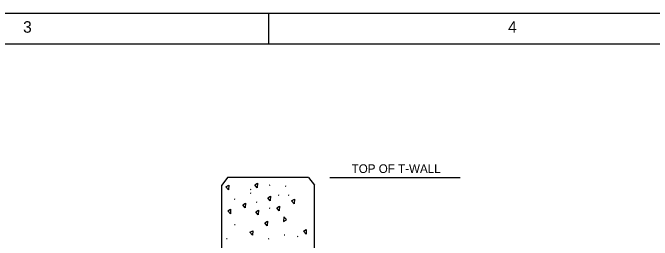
# Model space of a CAD drawing. Extents: x 22369.6 to 22389.4, y 22369.6 to 22386.
# Drawn here: x 22376.584 to 22380.038, y 22379.725 to 22380.956 of the extents above; entities that cross this region are included whole.
import ezdxf

# ---------------------------------------------------------------- set-up
doc = ezdxf.new("R2010")
doc.units = 0
for name, color, linetype in [('Level 1', 7, 'Continuous'), ('Level 10', 7, 'Continuous'), ('Level 4', 7, 'Continuous'), ('Level 44', 7, 'Continuous'), ('Level 7', 7, 'Continuous'), ('Level 9', 7, 'Continuous')]:
    doc.layers.add(name, color=color, linetype=linetype)

msp = doc.modelspace()

# ---------------------------------------------------------------- linework, layer by layer
at = {"layer": 'Level 1'}
msp.add_line((22378.2968, 22380.0639), (22379.0009, 22380.0639), dxfattribs=at)
msp.add_lwpolyline([(22369.6213, 22380.9546), (22384.2881, 22380.9546), (22384.2881, 22369.6213), (22369.6213, 22369.6213)], close=True, dxfattribs=at)
at = {"layer": 'Level 10'}
msp.add_line((22377.9681, 22380.788), (22377.9681, 22380.956), dxfattribs=at)
at = {"layer": 'Level 44'}
for p, q in [((22377.9705, 22380.0221), (22377.9743, 22380.0244)), ((22378.055, 22380.0189), (22378.059, 22380.0169)), ((22377.866, 22379.9811), (22377.87, 22379.9791)), ((22377.8687, 22379.9991), (22377.8725, 22380.0014)), ((22377.7796, 22379.9487), (22377.7836, 22379.9467)), ((22378.0172, 22379.9703), (22378.0212, 22379.9683)), ((22378.0712, 22379.9703), (22378.0752, 22379.9683)), ((22377.8984, 22379.9324), (22377.9024, 22379.9304)), ((22377.9686, 22379.9), (22377.9726, 22379.898)), ((22377.7814, 22379.8101), (22377.785, 22379.8098)), ((22378.0504, 22379.7534), (22378.0537, 22379.7536)), ((22378.1198, 22379.7473), (22378.1238, 22379.7453)), ((22377.7393, 22379.7339), (22377.7426, 22379.7344)), ((22377.9651, 22379.7317), (22377.9689, 22379.7339))]:
    msp.add_line(p, q, dxfattribs=at)
for points in [[(22377.7503, 22379.9982), (22377.736, 22380.0142), (22377.752, 22380.0227)], [(22377.9052, 22380.0085), (22377.891, 22380.0245), (22377.9069, 22380.033)], [(22377.9754, 22379.9382), (22377.9612, 22379.9542), (22377.9771, 22379.9627)], [(22378.105, 22379.922), (22378.0907, 22379.938), (22378.1066, 22379.9465)], [(22377.8404, 22379.9004), (22377.8262, 22379.9164), (22377.8421, 22379.9249)], [(22378.024, 22379.8842), (22378.0097, 22379.9002), (22378.0257, 22379.9087)], [(22377.7595, 22379.868), (22377.7452, 22379.884), (22377.7611, 22379.8925)], [(22377.9106, 22379.8626), (22377.8964, 22379.8786), (22377.9123, 22379.8871)], [(22378.0472, 22379.8255), (22378.0632, 22379.8376), (22378.0479, 22379.8512)], [(22377.9592, 22379.8031), (22377.945, 22379.8191), (22377.9609, 22379.8276)], [(22377.8789, 22379.7522), (22377.8646, 22379.7682), (22377.8805, 22379.7767)], [(22378.1682, 22379.7582), (22378.154, 22379.7742), (22378.1699, 22379.7827)]]:
    msp.add_lwpolyline(points, close=True, dxfattribs=at)
at = {"layer": 'Level 7'}
for p, q in [((22377.7445, 22380.0639), (22377.7133, 22380.0223)), ((22378.182, 22380.0639), (22377.7445, 22380.0639)), ((22378.182, 22380.0639), (22378.2133, 22380.0223)), ((22377.7133, 22378.6139), (22377.7133, 22380.0223)), ((22378.2133, 22378.6139), (22378.2133, 22380.0223))]:
    msp.add_line(p, q, dxfattribs=at)
at = {"layer": 'Level 9'}
msp.add_line((22370.1213, 22380.788), (22383.2041, 22380.788), dxfattribs=at)

# ---------------------------------------------------------------- texts
at = {"layer": 'Level 1'}
for s, p in [('3', (22376.6401, 22380.848)), ('4', (22379.2601, 22380.848))]:
    msp.add_text(s, height=0.0624, dxfattribs=at).set_placement(p)
at = {"layer": 'Level 4'}
msp.add_text('TOP OF T-WALL', height=0.046875, dxfattribs=at).set_placement((22378.4148, 22380.089))

doc.saveas('drawing.dxf')
